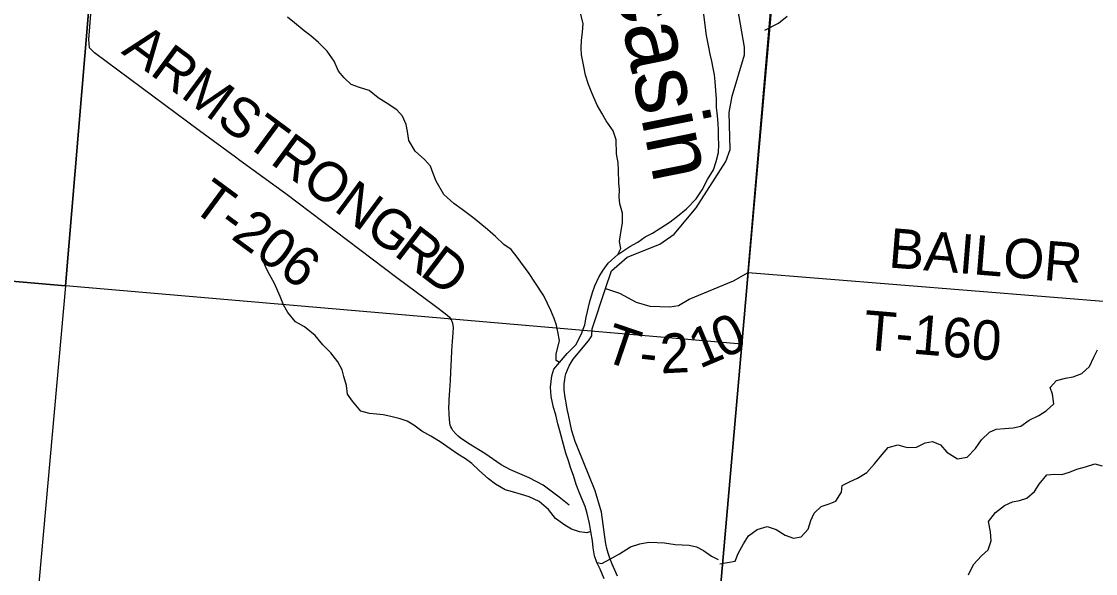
# Model space of a CAD drawing. Extents: x 0 to 42.5, y 0 to 22.
# Drawn here: x 7.815 to 8.588, y 17.417 to 17.814 of the extents above; entities that cross this region are included whole.
import ezdxf

# ---------------------------------------------------------------- set-up
doc = ezdxf.new("R2010")
doc.units = 0
for name, color, linetype in [('GM_X_Interchange_Ramps', 7, 'Continuous'), ('GM_X_Minor_River', 7, 'Continuous'), ('GM_X_Minor_River_Text', 7, 'Continuous'), ('GM_X_Section', 7, 'Continuous'), ('GM_X_Township', 7, 'Continuous'), ('GM_X_Township_Road', 7, 'Continuous'), ('GM_X_Township_Road_Text', 7, 'Continuous'), ('SH_Cut_Line', 7, 'Continuous')]:
    doc.layers.add(name, color=color, linetype=linetype)

msp = doc.modelspace()

# ---------------------------------------------------------------- linework, layer by layer
at = {"layer": 'GM_X_Interchange_Ramps'}
msp.add_lwpolyline([(8.9, 15.53758), (8.9, 19.05381), (8.80207, 19.06082), (8.79715, 19.06117), (8.45529, 19.08562), (8.42249, 18.59682), (8.4216, 18.58362), (8.41233, 18.47844), (8.38323, 18.14846), (8.33786, 17.63394), (8.30797, 17.29222), (8.30866, 17.28459), (8.30841, 17.27648), (8.30737, 17.26941), (8.29023, 17.08765), (8.28773, 17.0646), (8.28228, 16.99116), (8.27401, 16.89234), (8.25723, 16.70556), (8.24802, 16.59431), (8.24781, 16.59008), (8.17933, 15.79111)], dxfattribs=at)
at = {"layer": 'GM_X_Minor_River'}
for p, q in [((8.3499, 17.80797), (8.35968, 17.81309)), ((8.35968, 17.81309), (8.36615, 17.81799)), ((8.58356, 17.56607), (8.58681, 17.57269)), ((8.58681, 17.57269), (8.58949, 17.57799)), ((8.57823, 17.56097), (8.58356, 17.56607)), ((8.55525, 17.551), (8.55982, 17.55611)), ((8.55982, 17.55611), (8.56647, 17.5576)), ((8.56647, 17.5576), (8.57197, 17.55872)), ((8.57197, 17.55872), (8.57823, 17.56097)), ((8.55694, 17.54626), (8.55525, 17.551)), ((8.55786, 17.53924), (8.55694, 17.54626)), ((8.54721, 17.53093), (8.55253, 17.53414)), ((8.55253, 17.53414), (8.55786, 17.53924)), ((8.53428, 17.52321), (8.54018, 17.52736)), ((8.54018, 17.52736), (8.54721, 17.53093)), ((8.50599, 17.51326), (8.5117, 17.51874)), ((8.5117, 17.51874), (8.51645, 17.521)), ((8.51645, 17.521), (8.52252, 17.52136)), ((8.52252, 17.52136), (8.52878, 17.5219)), ((8.52878, 17.5219), (8.53428, 17.52321)), ((8.43885, 17.50783), (8.44568, 17.5097)), ((8.44568, 17.5097), (8.4525, 17.50778)), ((8.45914, 17.50814), (8.46541, 17.51115)), ((8.46541, 17.51115), (8.47053, 17.51207)), ((8.47053, 17.51207), (8.4764, 17.50978)), ((8.4764, 17.50978), (8.48093, 17.50445)), ((8.50161, 17.50702), (8.50599, 17.51326)), ((8.42895, 17.49611), (8.43447, 17.50273)), ((8.43447, 17.50273), (8.43885, 17.50783)), ((8.4525, 17.50778), (8.45914, 17.50814)), ((8.48093, 17.50445), (8.48869, 17.49968)), ((8.49552, 17.50079), (8.50161, 17.50702)), ((8.42342, 17.48988), (8.42895, 17.49611)), ((8.48869, 17.49968), (8.49552, 17.50079)), ((8.58081, 17.49382), (8.58746, 17.49607)), ((8.58746, 17.49607), (8.59276, 17.49454)), ((8.41677, 17.48573), (8.42342, 17.48988)), ((8.54739, 17.48143), (8.55292, 17.48824)), ((8.55292, 17.48824), (8.55861, 17.4886)), ((8.55861, 17.4886), (8.56372, 17.48839)), ((8.56372, 17.48839), (8.56923, 17.49007)), ((8.56923, 17.49007), (8.57455, 17.49214)), ((8.57455, 17.49214), (8.58081, 17.49382)), ((8.40516, 17.47572), (8.40556, 17.48046)), ((8.40556, 17.48046), (8.41145, 17.48328)), ((8.41145, 17.48328), (8.41677, 17.48573)), ((8.54415, 17.47614), (8.54739, 17.48143)), ((8.40097, 17.46929), (8.40516, 17.47572)), ((8.53331, 17.46973), (8.53844, 17.47142)), ((8.53844, 17.47142), (8.54415, 17.47614)), ((8.38538, 17.46063), (8.39052, 17.46535)), ((8.39052, 17.46535), (8.39622, 17.46722)), ((8.39622, 17.46722), (8.40097, 17.46929)), ((8.51602, 17.46107), (8.52249, 17.46598)), ((8.52249, 17.46598), (8.52819, 17.4688)), ((8.52819, 17.4688), (8.53331, 17.46973)), ((8.38309, 17.45533), (8.38538, 17.46063)), ((8.51088, 17.45465), (8.51602, 17.46107)), ((8.33811, 17.44431), (8.34438, 17.44884)), ((8.34438, 17.44884), (8.3516, 17.45109)), ((8.3516, 17.45109), (8.35803, 17.44879)), ((8.35803, 17.44879), (8.36465, 17.44478)), ((8.37621, 17.4436), (8.38117, 17.44908)), ((8.38117, 17.44908), (8.38309, 17.45533)), ((8.51237, 17.44705), (8.51088, 17.45465)), ((8.33467, 17.43844), (8.33811, 17.44431)), ((8.36465, 17.44478), (8.37071, 17.44267)), ((8.37071, 17.44267), (8.37621, 17.4436)), ((8.5108, 17.43416), (8.51291, 17.44079)), ((8.51291, 17.44079), (8.51237, 17.44705)), ((8.33085, 17.43163), (8.33467, 17.43844)), ((8.50585, 17.43001), (8.5108, 17.43416)), ((8.31748, 17.42408), (8.32855, 17.42595)), ((8.32855, 17.42595), (8.33085, 17.43163)), ((8.50014, 17.42359), (8.50585, 17.43001)), ((8.4965, 17.4162), (8.50014, 17.42359))]:
    msp.add_line(p, q, dxfattribs=at)
for points in [[(8.21405, 17.48123), (8.21216, 17.48769), (8.21027, 17.49282), (8.20858, 17.49813), (8.20669, 17.50364), (8.20424, 17.51256), (8.20235, 17.51978), (8.20103, 17.5249), (8.19953, 17.53136), (8.19783, 17.53667), (8.19614, 17.54446), (8.19558, 17.5511), (8.19654, 17.55945), (8.19807, 17.56419), (8.20206, 17.56892), (8.20758, 17.57536), (8.21385, 17.58161), (8.21766, 17.58901), (8.22032, 17.59602), (8.22128, 17.60152), (8.22396, 17.6129), (8.22587, 17.61935), (8.22758, 17.62409), (8.23063, 17.63073), (8.23368, 17.63546), (8.23729, 17.64039), (8.24413, 17.64664), (8.25287, 17.65232), (8.25856, 17.65553), (8.26388, 17.65931), (8.26901, 17.66196), (8.27509, 17.66574), (8.28192, 17.67009), (8.28705, 17.67407), (8.2937, 17.67956), (8.30055, 17.68676), (8.30492, 17.6932), (8.30873, 17.70059), (8.31291, 17.7076), (8.31501, 17.71348), (8.31673, 17.71993), (8.31693, 17.72581), (8.31656, 17.73094), (8.31657, 17.73606), (8.31639, 17.7408), (8.31583, 17.74631), (8.31527, 17.75257), (8.31509, 17.75864), (8.31473, 17.76453), (8.31417, 17.77098), (8.3138, 17.77572), (8.31286, 17.78066), (8.31173, 17.78559), (8.3106, 17.79072), (8.30966, 17.79566), (8.30797, 17.80401), (8.30685, 17.8135), (8.3061, 17.81938)], [(8.24413, 17.64664), (8.24641, 17.651), (8.24528, 17.65594), (8.24643, 17.66238), (8.24759, 17.6694), (8.2476, 17.67623), (8.24552, 17.68307), (8.24515, 17.688), (8.24535, 17.69313), (8.24498, 17.69806), (8.24462, 17.70717), (8.24444, 17.71248), (8.24331, 17.71913), (8.24295, 17.72899), (8.24087, 17.73545), (8.23577, 17.74286), (8.23255, 17.74837), (8.22934, 17.75407), (8.22537, 17.7628), (8.2231, 17.76888), (8.22084, 17.77553), (8.21952, 17.78293), (8.21802, 17.79033), (8.21784, 17.79508), (8.21804, 17.80058), (8.2188, 17.80646), (8.2192, 17.81272), (8.21712, 17.82126)], [(8.20206, 17.56892), (8.19979, 17.57026), (8.1998, 17.575), (8.20209, 17.58486), (8.20096, 17.59094), (8.20002, 17.59568), (8.19833, 17.60062), (8.19587, 17.60632), (8.1936, 17.61126), (8.19096, 17.61695), (8.18452, 17.62683), (8.18036, 17.63291), (8.17166, 17.64469), (8.1673, 17.65021), (8.162, 17.65382), (8.15613, 17.65953), (8.15025, 17.66466), (8.14078, 17.67246), (8.13207, 17.67893), (8.126, 17.6833), (8.119, 17.68977), (8.11351, 17.69927), (8.11125, 17.70478), (8.10936, 17.71009), (8.105, 17.71484), (8.09818, 17.72093), (8.09364, 17.72853), (8.09271, 17.73517), (8.09177, 17.74011), (8.08912, 17.746), (8.08515, 17.75075), (8.07738, 17.7557), (8.07169, 17.75931), (8.06525, 17.76464), (8.05824, 17.76674), (8.05217, 17.76884), (8.04725, 17.77359), (8.04308, 17.77853), (8.04006, 17.78575), (8.03495, 17.79278), (8.0287, 17.79906), (8.02321, 17.804), (8.01847, 17.80742), (8.01146, 17.81313), (8.00635, 17.81732)], [(8.2248, 17.44744), (8.22195, 17.44649), (8.21645, 17.44707), (8.21076, 17.44898), (8.20603, 17.45184), (8.19921, 17.45679), (8.19428, 17.46325), (8.18747, 17.46895), (8.18045, 17.47238), (8.17476, 17.4741), (8.16832, 17.47601), (8.16301, 17.47735), (8.15618, 17.48135), (8.15107, 17.48515), (8.14425, 17.49124), (8.13914, 17.49618), (8.1344, 17.49961), (8.12891, 17.50303), (8.12341, 17.50684), (8.11621, 17.51198), (8.10958, 17.51598), (8.10313, 17.51959), (8.09726, 17.52397), (8.09252, 17.52683), (8.0874, 17.52835), (8.08077, 17.53007), (8.07527, 17.53122), (8.07034, 17.5318), (8.0654, 17.53219), (8.05915, 17.53391), (8.05309, 17.54113), (8.04968, 17.54626), (8.04875, 17.55234), (8.04705, 17.55879), (8.04573, 17.56373), (8.04252, 17.56943), (8.03759, 17.57589), (8.03172, 17.58159), (8.02623, 17.58825), (8.01866, 17.59452), (8.01221, 17.59814), (8.00672, 17.60479), (8.00351, 17.6103), (8.00105, 17.61638), (7.99709, 17.62587), (7.99349, 17.63214), (7.99104, 17.63689), (7.98877, 17.64202)], [(8.23441, 17.41326), (8.23139, 17.42029), (8.22893, 17.42504), (8.22742, 17.42979), (8.22649, 17.43567), (8.22593, 17.44079), (8.2248, 17.44744), (8.22386, 17.45313), (8.22217, 17.46035), (8.22066, 17.46547), (8.21669, 17.4744), (8.21405, 17.48123)], [(8.22893, 17.42504), (8.23273, 17.42446), (8.23899, 17.42768), (8.24526, 17.43127), (8.25324, 17.43637), (8.25988, 17.43845), (8.26652, 17.43976), (8.2724, 17.43956), (8.27771, 17.43917), (8.28549, 17.43802), (8.29042, 17.43782), (8.29554, 17.43762), (8.30085, 17.43628), (8.30578, 17.43381), (8.31166, 17.42962), (8.31639, 17.42733)]]:
    msp.add_lwpolyline(points, dxfattribs=at)
at = {"layer": 'GM_X_Section'}
for points in [[(7.88871, 18.12341), (7.84665, 17.62408), (7.35243, 17.66688), (7.39563, 18.16469)], [(7.88871, 18.12341), (8.37679, 18.08863), (8.33774, 17.63462), (8.33335, 17.58203), (7.84665, 17.62408)], [(7.35243, 17.66688), (7.84665, 17.62408), (7.80193, 17.12684), (7.30959, 17.16207)]]:
    msp.add_lwpolyline(points, close=True, dxfattribs=at)
at = {"layer": 'GM_X_Township'}
msp.add_lwpolyline([(7.68737, 18.6472), (7.92905, 18.62689), (8.11105, 18.61092), (8.2565, 18.59969), (8.27414, 18.60201), (8.28296, 18.60185), (8.29503, 18.59876), (8.30146, 18.59566), (8.4216, 18.58362), (8.41233, 18.47844), (8.38323, 18.14846), (8.33786, 17.63394), (8.30797, 17.29222)], dxfattribs=at)
at = {"layer": 'GM_X_Township_Road'}
msp.add_line((8.33797, 17.63368), (8.81327, 17.5954), dxfattribs=at)
for points in [[(7.87917, 18.01606), (7.87848, 18.00405), (7.87171, 17.91073), (7.86324, 17.80122), (7.86364, 17.79557)], [(8.24381, 17.41535), (8.24013, 17.42392), (8.23843, 17.42826), (8.23725, 17.43179), (8.23634, 17.43509), (8.23562, 17.43843), (8.23482, 17.44364), (8.23233, 17.46118), (8.22794, 17.47672), (8.21504, 17.50803), (8.21348, 17.51209), (8.21223, 17.51593), (8.21116, 17.51983), (8.21015, 17.52438), (8.20871, 17.53138), (8.20776, 17.53532), (8.20688, 17.5399), (8.20663, 17.54142), (8.20622, 17.54387), (8.20564, 17.54911), (8.20552, 17.55128), (8.20563, 17.55376), (8.2059, 17.55654), (8.20636, 17.55898), (8.20684, 17.56078), (8.20787, 17.56371), (8.20913, 17.56655), (8.21052, 17.56897), (8.21211, 17.57126), (8.22294, 17.58446), (8.22537, 17.58804), (8.22561, 17.59318), (8.23531, 17.62209), (8.23959, 17.63483), (8.25089, 17.64477), (8.2745, 17.65399), (8.28482, 17.66128), (8.3006, 17.68029), (8.32186, 17.7135), (8.325, 17.72202), (8.32439, 17.74864), (8.32643, 17.76059), (8.33533, 17.79014), (8.33521, 17.79585), (8.32605, 17.84957)], [(7.96893, 17.7165), (7.94299, 17.73546), (7.86749, 17.79157), (7.86364, 17.79557)], [(8.2092, 17.46626), (8.20183, 17.47219), (8.19049, 17.48076), (8.18037, 17.48601), (8.17191, 17.48949), (8.16693, 17.49165), (8.16013, 17.49538), (8.14833, 17.50343), (8.13664, 17.51078), (8.13071, 17.5147), (8.12912, 17.51593), (8.12747, 17.51767), (8.12543, 17.52012), (8.12457, 17.52143), (8.12405, 17.52256), (8.12357, 17.52388), (8.12321, 17.52556), (8.1229, 17.52822), (8.12266, 17.53168), (8.12255, 17.53709), (8.12266, 17.53962), (8.12279, 17.54198), (8.12324, 17.54915), (8.12361, 17.55566), (8.12392, 17.56216), (8.12442, 17.5713), (8.12475, 17.57733), (8.12518, 17.58414), (8.12557, 17.59031), (8.12576, 17.59404), (8.12567, 17.59568), (8.12544, 17.59697), (8.12497, 17.59853), (8.12422, 17.59997), (8.12344, 17.60101), (8.12259, 17.60181), (8.1216, 17.6026), (8.11991, 17.60395), (8.11289, 17.60918), (8.08509, 17.62988), (8.00514, 17.6902), (7.97207, 17.7142), (7.96893, 17.7165)], [(8.23531, 17.62209), (8.24544, 17.61879), (8.2573, 17.61238), (8.2673, 17.6094), (8.28151, 17.60904), (8.28777, 17.60992), (8.29541, 17.61439), (8.3274, 17.62769), (8.33797, 17.63368)]]:
    msp.add_lwpolyline(points, dxfattribs=at)
at = {"layer": 'SH_Cut_Line'}
for points in [[(8.9, 14.1), (8.9, 19.05381), (8.80207, 19.06082), (8.79715, 19.06117), (8.45529, 19.08562), (8.42249, 18.59682), (8.4216, 18.58362), (8.41233, 18.47844), (8.38323, 18.14846), (8.33786, 17.63394), (8.30797, 17.29222), (8.30866, 17.28459), (8.30841, 17.27648), (8.30737, 17.26941), (8.29023, 17.08765), (8.28773, 17.0646), (8.28228, 16.99116), (8.27401, 16.89234), (8.25723, 16.70556), (8.24802, 16.59431), (8.24781, 16.59008), (8.17933, 15.79111)], [(8.30797, 17.29222), (8.33786, 17.63394), (8.38323, 18.14846), (8.41233, 18.47844), (8.4216, 18.58362), (8.30146, 18.59566), (8.29503, 18.59876), (8.28296, 18.60185), (8.27414, 18.60201), (8.2565, 18.59969), (8.11105, 18.61092), (7.92905, 18.62689), (7.68737, 18.6472)]]:
    msp.add_lwpolyline(points, dxfattribs=at)

# ---------------------------------------------------------------- texts
at = {"layer": 'GM_X_Minor_River_Text'}
msp.add_text('Moccasin', height=0.047349, rotation=281.44705, dxfattribs=at).set_placement((8.21753, 17.95899))
at = {"layer": 'GM_X_Township_Road_Text'}
for s, height, rotation, p in [('ARMSTRONG', 0.028409, 323.50027, (7.88615, 17.79175)), ('T-206', 0.028409, 323.62677, (7.93611, 17.67972)), ('R', 0.02841, 322.52279, (8.08216, 17.64661)), ('BAILOR', 0.028409, 355.37419, (8.43847, 17.63736)), ('D', 0.02841, 322.83696, (8.10081, 17.63232)), ('0', 0.02841, 24.16887, (8.31965, 17.5713)), ('T-160', 0.028409, 355.21346, (8.42012, 17.57833)), ('T', 0.02841, 341.19714, (8.23206, 17.57075)), ('1', 0.02841, 22.74246, (8.30293, 17.56428)), ('2', 0.02841, 2.87391, (8.27517, 17.56104)), ('-', 0.02841, 353.75815, (8.25876, 17.56244))]:
    msp.add_text(s, height=height, rotation=rotation, dxfattribs=at).set_placement(p)

doc.saveas('drawing.dxf')
